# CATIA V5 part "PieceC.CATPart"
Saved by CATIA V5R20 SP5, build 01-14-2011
Part number: PieceC
Bounding box of the stored display mesh (mm): x -20.997 to 20.997, y -20.998 to 20.998, z -63 to 10
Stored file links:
  D:\thinkmotion-MPB\Dropbox\IAO\IAO_2010\iao\IAO OK\IAO_2010_1447_melguidj\Catia_1447_melguidj\PieceC.CATPart
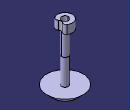
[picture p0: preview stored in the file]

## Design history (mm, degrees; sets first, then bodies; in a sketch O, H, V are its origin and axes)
Body1 (main body)
  Sketch1 on xy-plane, origin (0, 0, 0), H (1, 0, 0), V (0, 1, 0)
    point P1 (0, 0)
    point P2 (0, -12.5)
    circle A1 centre (0, 0) radius 4
    arc A2 centre (0, 0) radius 8.58 from (4.576, 7.2579) to (4.576, -7.2579) ccw
    axis line L1 (12.8244, 2.0574) -> (9.7271, 4.0102)
    point P5 (4.576, 7.2579)
    point P6 (4.576, -7.2579)
    arc A3 centre (2.7456, 4.3547) radius 3.432 from (4.576, 7.2579) to (5.3985, 2.1774) cw
    arc A4 centre (8.0513, 0) radius 3.432 from (5.3985, 2.1774) to (5.3985, -2.1774) ccw
    arc A5 centre (2.7456, -4.3547) radius 3.432 from (5.3985, -2.1774) to (4.576, -7.2579) cw
    point P12 (4.576, -7.2579)
    radius A1 = 4
    radius A2 = 8.58
    radius A3 = 3.432 {= Sketch1.radius(A5)}
    radius A4 = 3.432 {= Sketch1.radius(A5)}
    radius A5 = 3.432
    distance P5 V = 4.576 {= Sketch1.distance(P6 V)}
    distance P6 V = 4.576
    coincidence: P1 V, P2 V, P1 O, L1 P5, A5 P12, P12 A2
    tangency: L1 A2, A3 A2, A4 A3, A5 A4, A5 A2
    concentricity: A2 A1
  Pad1: profile Sketch1, direction (0, 0, 1), length 10
  Sketch2 on start face of Pad1, origin (0, 0, 0), H (1, 0, 0), V (0, -1, 0)
    circle A1 centre (0, 0) radius 4
    reference projected circle E1 centre (0, 0) radius 4 from edge [face of Pad1 from Sketch1.A1 | start face of Pad1]
    coincidence: A1 E1
  Pad2: profile Sketch2, direction (0, 0, -1), length 45
  Plane1: stored without definition
  DatumCurve1
  DatumCurve2
  DatumSurface1
  Sketch3 on Plane1, origin (0, 0, 0), H (-0.2368, -0.9715, 0), V (0, 0, 1)
    point P1 (0, -26.0088)
    line L1 (0, -26.0088) -> (0, -63)
    line L2 (0, -63) -> (-14, -63)
    line L3 (-14, -63) -> (-21, -56)
    line L4 (-21, -56) -> (-4, -56)
    line L5 (-4, -56) -> (-4, -26.0088)
    line L6 (-4, -26.0088) -> (0, -26.0088)
    reference projected line E1 through (0, -77) direction (1, 0) from edge of DatumCurve2
    length L6 = 4
    angle L3 L2 = 45
    distance L2 E1 = 14
    distance L2 L4 = 7
    length L2 = 14
    coincidence: P1 V
    vertical: L1 V, L5 V
    horizontal: L2 H, L4 H, L6 H
  Shaft1: profile Sketch3, axis Sketch3.L1, angle 360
